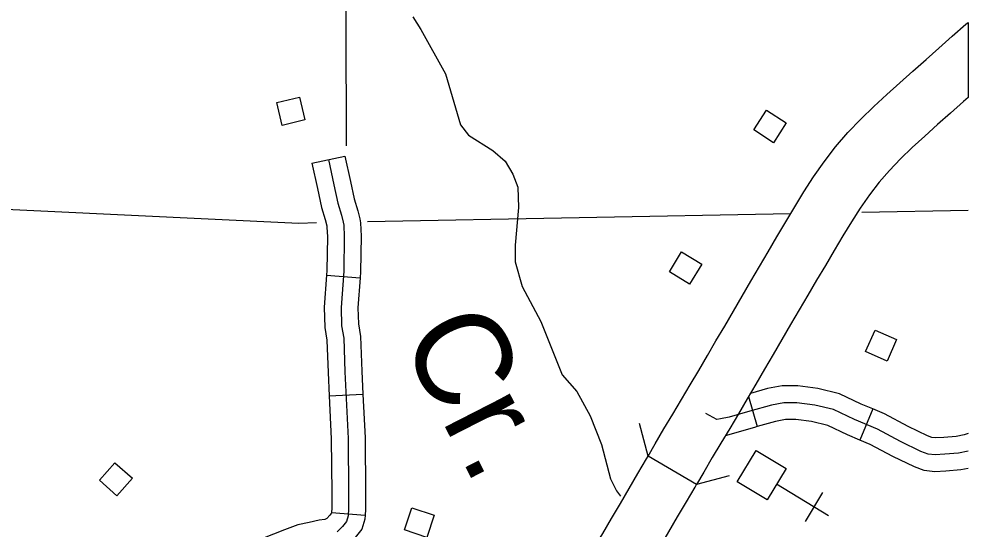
# Model space of a CAD drawing. Extents: x 1370130 to 1380143, y 377636 to 380256.
# Drawn here: x 1377650 to 1377768.2, y 379128.7 to 379192.1 of the extents above; entities that cross this region are included whole.
import ezdxf

# ---------------------------------------------------------------- set-up
doc = ezdxf.new("R2010")
doc.units = 0
for name, color, linetype in [('Level 15', 7, 'Continuous'), ('Level 32', 7, 'Continuous'), ('Level 35', 7, 'Continuous'), ('Level 37', 7, 'Continuous'), ('Level 4', 7, 'Continuous'), ('Level 5', 7, 'Continuous'), ('Level 56', 7, 'Continuous'), ('Level 57', 7, 'Continuous')]:
    doc.layers.add(name, color=color, linetype=linetype)

msp = doc.modelspace()

# ---------------------------------------------------------------- linework, layer by layer
at = {"layer": 'Level 15'}
for p, q in [((1377767.86, 379191.46), (1377768.15, 379191.69)), ((1377768.15, 379191.69), (1377768.15, 379182.36)), ((1377766.16, 379189.98), (1377767.86, 379191.46)), ((1377764.53, 379188.51), (1377766.16, 379189.98)), ((1377762.92, 379187.07), (1377764.53, 379188.51)), ((1377761.3, 379185.64), (1377762.92, 379187.07)), ((1377759.68, 379184.19), (1377761.3, 379185.64)), ((1377758.06, 379182.74), (1377759.68, 379184.19)), ((1377756.42, 379181.24), (1377758.06, 379182.74)), ((1377768.15, 379182.36), (1377767.57, 379181.84)), ((1377754.79, 379179.67), (1377756.42, 379181.24)), ((1377767.57, 379181.84), (1377765.95, 379180.41)), ((1377765.95, 379180.41), (1377764.35, 379178.98)), ((1377753.19, 379178), (1377754.79, 379179.67)), ((1377764.35, 379178.98), (1377762.76, 379177.55)), ((1377751.65, 379176.22), (1377753.19, 379178)), ((1377762.76, 379177.55), (1377761.21, 379176.13)), ((1377750.24, 379174.36), (1377751.65, 379176.22)), ((1377761.21, 379176.13), (1377759.74, 379174.72)), ((1377748.93, 379172.5), (1377750.24, 379174.36)), ((1377759.74, 379174.72), (1377758.36, 379173.28)), ((1377758.36, 379173.28), (1377757.09, 379171.81)), ((1377747.71, 379170.61), (1377748.93, 379172.5)), ((1377757.09, 379171.81), (1377755.89, 379170.23)), ((1377746.57, 379168.74), (1377747.71, 379170.61)), ((1377755.89, 379170.23), (1377754.73, 379168.59)), ((1377745.46, 379166.88), (1377746.57, 379168.74)), ((1377754.73, 379168.59), (1377753.64, 379166.89)), ((1377744.36, 379165.01), (1377745.46, 379166.88)), ((1377753.64, 379166.89), (1377752.56, 379165.12)), ((1377743.27, 379163.16), (1377744.36, 379165.01)), ((1377752.56, 379165.12), (1377751.48, 379163.31)), ((1377742.19, 379161.34), (1377743.27, 379163.16)), ((1377751.48, 379163.31), (1377750.39, 379161.46)), ((1377741.11, 379159.51), (1377742.19, 379161.34)), ((1377750.39, 379161.46), (1377749.3, 379159.61)), ((1377749.3, 379159.61), (1377748.22, 379157.77)), ((1377740.02, 379157.65), (1377741.11, 379159.51)), ((1377738.93, 379155.78), (1377740.02, 379157.65)), ((1377748.22, 379157.77), (1377747.14, 379155.95)), ((1377737.85, 379153.92), (1377738.93, 379155.78)), ((1377747.14, 379155.95), (1377746.06, 379154.12)), ((1377736.76, 379152.07), (1377737.85, 379153.92)), ((1377746.06, 379154.12), (1377744.98, 379152.26)), ((1377735.7, 379150.23), (1377736.76, 379152.07)), ((1377744.98, 379152.26), (1377743.89, 379150.39)), ((1377734.63, 379148.4), (1377735.7, 379150.23)), ((1377743.89, 379150.39), (1377742.82, 379148.55)), ((1377733.55, 379146.58), (1377734.63, 379148.4)), ((1377742.82, 379148.55), (1377741.75, 379146.7)), ((1377741.75, 379146.7), (1377740.66, 379144.85)), ((1377732.48, 379144.77), (1377733.55, 379146.58)), ((1377731.39, 379142.96), (1377732.48, 379144.77)), ((1377740.66, 379144.85), (1377739.57, 379143.01)), ((1377730.29, 379141.12), (1377731.39, 379142.96)), ((1377739.57, 379143.01), (1377738.48, 379141.18)), ((1377729.2, 379139.27), (1377730.29, 379141.12)), ((1377738.48, 379141.18), (1377737.39, 379139.36)), ((1377728.31, 379137.74), (1377729.2, 379139.27)), ((1377737.39, 379139.36), (1377736.31, 379137.54)), ((1377734.36, 379134.21), (1377728.31, 379137.74)), ((1377736.31, 379137.54), (1377735.24, 379135.73)), ((1377735.24, 379135.73), (1377734.36, 379134.21))]:
    msp.add_line(p, q, dxfattribs=at)
for points in [[(1377720.96, 379125.36), (1377721.6, 379126.35), (1377722.68, 379128.12), (1377723.76, 379129.97), (1377724.86, 379131.85), (1377725.95, 379133.72), (1377727.04, 379135.56), (1377728.12, 379137.41), (1377728.31, 379137.74)], [(1377726.81, 379121.52), (1377727.53, 379122.61), (1377728.7, 379124.54), (1377729.81, 379126.45), (1377730.9, 379128.31), (1377731.99, 379130.17), (1377733.08, 379132.03), (1377734.16, 379133.88), (1377734.36, 379134.21)]]:
    msp.add_lwpolyline(points, dxfattribs=at)
at = {"layer": 'Level 32'}
for p, q in [((1377686.45, 379174.18), (1377690.56, 379175.07)), ((1377688.27, 379160.23), (1377692.46, 379159.91)), ((1377688.6, 379145.22), (1377692.8, 379145.43)), ((1377740.82, 379145.13), (1377741.89, 379141.4)), ((1377756.29, 379143.6), (1377754.68, 379139.73)), ((1377688.89, 379130.71), (1377693.08, 379130.39))]:
    msp.add_line(p, q, dxfattribs=at)
for points in [[(1377690.56, 379175.07), (1377691.24, 379171.92), (1377691.7, 379169.75), (1377692.17, 379168.27), (1377692.4, 379167.26), (1377692.51, 379166.74), (1377692.59, 379165.08), (1377692.52, 379160.64), (1377692.46, 379159.91)], [(1377686.45, 379174.18), (1377687.13, 379171.03), (1377687.63, 379168.68), (1377688.12, 379167.16), (1377688.3, 379166.38), (1377688.33, 379166.22), (1377688.39, 379165.01), (1377688.32, 379160.83), (1377688.27, 379160.23)], [(1377688.5, 379174.62), (1377689.19, 379171.48), (1377689.67, 379169.22), (1377690.15, 379167.71), (1377690.35, 379166.82), (1377690.42, 379166.48), (1377690.49, 379165.04), (1377690.42, 379160.73), (1377690.08, 379156.22), (1377690.15, 379153.96), (1377690.42, 379152.39), (1377690.56, 379148.21), (1377690.97, 379139.94), (1377691.03, 379133.16), (1377691.03, 379131.18), (1377690.97, 379130.29), (1377690.76, 379129.6), (1377690.28, 379128.99), (1377689.6, 379128.3)], [(1377688.27, 379160.23), (1377687.97, 379156.27), (1377688.05, 379153.75), (1377688.32, 379152.17), (1377688.46, 379148.13), (1377688.6, 379145.22)], [(1377692.46, 379159.91), (1377692.18, 379156.17), (1377692.24, 379154.17), (1377692.51, 379152.6), (1377692.65, 379148.3), (1377692.8, 379145.43)], [(1377692.8, 379145.43), (1377693.07, 379140), (1377693.13, 379133.17), (1377693.13, 379131.1), (1377693.08, 379130.39)], [(1377756.29, 379143.6), (1377754.85, 379144.2), (1377752.13, 379145.5), (1377749.45, 379146.16), (1377746.97, 379146.48), (1377745.03, 379146.48), (1377743.19, 379146.14), (1377741.07, 379145.53)], [(1377688.6, 379145.22), (1377688.87, 379139.87), (1377688.93, 379133.15), (1377688.93, 379131.26), (1377688.89, 379130.71)], [(1377768.15, 379138.33), (1377766.96, 379138.09), (1377765.25, 379137.96), (1377764.06, 379137.9), (1377763.19, 379137.99), (1377762.28, 379138.32), (1377759.74, 379139.54), (1377756.87, 379141.09), (1377754, 379142.28), (1377751.42, 379143.51), (1377749.06, 379144.09), (1377746.84, 379144.38), (1377745.22, 379144.38), (1377743.68, 379144.09), (1377740.97, 379143.32), (1377738.42, 379142.57), (1377737.32, 379142.38), (1377736.87, 379142.28), (1377735.52, 379143.04)], [(1377768.15, 379140.55), (1377767.66, 379140.38), (1377766.67, 379140.17), (1377765.12, 379140.06), (1377764.12, 379140), (1377763.66, 379140.05), (1377763.09, 379140.26), (1377760.69, 379141.41), (1377757.77, 379142.99), (1377756.29, 379143.6)], [(1377754.68, 379139.73), (1377753.14, 379140.37), (1377750.71, 379141.52), (1377748.67, 379142.02), (1377746.7, 379142.28), (1377745.42, 379142.28), (1377744.16, 379142.05), (1377741.89, 379141.4)], [(1377741.89, 379141.4), (1377741.55, 379141.3), (1377737.93, 379140.24)], [(1377768.15, 379136.19), (1377767.25, 379136.01), (1377765.39, 379135.86), (1377764, 379135.79), (1377762.71, 379135.93), (1377761.47, 379136.38), (1377758.78, 379137.67), (1377755.96, 379139.19), (1377754.68, 379139.73)], [(1377688.89, 379130.71), (1377688.89, 379130.68), (1377688.86, 379130.58), (1377688.7, 379130.38), (1377688.3, 379129.98), (1377688.08, 379129.85), (1377687.37, 379129.76), (1377686.13, 379129.47), (1377684.71, 379129.17), (1377683.04, 379128.56), (1377680.28, 379127.47), (1377677.99, 379126.17), (1377677.25, 379125.62)], [(1377693.08, 379130.39), (1377693.04, 379129.9), (1377692.66, 379128.63), (1377691.86, 379127.6), (1377690.89, 379126.63), (1377689.47, 379125.8), (1377688.13, 379125.62), (1377687.05, 379125.37), (1377685.87, 379125.12), (1377684.53, 379124.63), (1377682.1, 379123.67), (1377680.28, 379122.64), (1377679.74, 379122.24)]]:
    msp.add_lwpolyline(points, dxfattribs=at)
at = {"layer": 'Level 35'}
msp.add_lwpolyline([(1377699.04, 379192.4), (1377700.03, 379190.82), (1377703.09, 379185.3), (1377704.96, 379178.94), (1377705.94, 379177.67), (1377708.99, 379175.77), (1377710.5, 379174.43), (1377711.46, 379172.82), (1377712.08, 379171.21), (1377712.19, 379168.68), (1377711.75, 379163.96), (1377711.77, 379161.91), (1377712.62, 379158.84), (1377714.95, 379154.46), (1377717.62, 379147.84), (1377719.46, 379145.77), (1377721.12, 379142.75), (1377722.51, 379139.16), (1377723.64, 379134.91), (1377724.37, 379133.41), (1377724.88, 379132.75)], dxfattribs=at)
at = {"layer": 'Level 37'}
for points in [[(1377728.31, 379137.74), (1377727.24, 379141.8)], [(1377738.42, 379135.28), (1377734.36, 379134.21)]]:
    msp.add_lwpolyline(points, dxfattribs=at)
at = {"layer": 'Level 4'}
for points in [[(1377687.01, 379166.75), (1377684.84, 379166.69), (1377545.86, 379173.3), (1377543.53, 379173.41), (1377537.66, 379173.5)], [(1377746.07, 379167.87), (1377693.38, 379166.89)], [(1377768.15, 379168.29), (1377754.91, 379168.04)]]:
    msp.add_lwpolyline(points, dxfattribs=at)
at = {"layer": 'Level 5'}
msp.add_lwpolyline([(1377690.46, 379268.93), (1377690.72, 379176.34)], dxfattribs=at)
at = {"layer": 'Level 56'}
for points in [[(1377684.91, 379182.39), (1377685.59, 379179.56), (1377682.74, 379178.88), (1377682.07, 379181.71)], [(1377741.49, 379178.31), (1377743.06, 379180.76), (1377745.52, 379179.19), (1377743.95, 379176.73)], [(1377734.99, 379161.63), (1377733.46, 379159.14), (1377730.97, 379160.67), (1377732.49, 379163.15)], [(1377759.24, 379152.23), (1377758.07, 379149.56), (1377755.39, 379150.74), (1377756.57, 379153.41)], [(1377664.11, 379134.97), (1377662.17, 379132.79), (1377659.99, 379134.74), (1377661.93, 379136.91)], [(1377697.99, 379128.55), (1377698.91, 379131.31), (1377701.69, 379130.39), (1377700.76, 379127.62)]]:
    msp.add_lwpolyline(points, close=True, dxfattribs=at)
at = {"layer": 'Level 57'}
for p, q in [((1377750.76, 379130.31), (1377744.31, 379134.22)), ((1377750.05, 379133.2), (1377747.88, 379129.61))]:
    msp.add_line(p, q, dxfattribs=at)
msp.add_lwpolyline([(1377741.76, 379138.43), (1377745.49, 379136.17), (1377743.14, 379132.29), (1377739.41, 379134.55)], close=True, dxfattribs=at)

# ---------------------------------------------------------------- texts
at = {"layer": 'Level 35'}
msp.add_text('Cr.', height=11.827, rotation=297.0639, dxfattribs=at).set_placement((1377697.33, 379152.5))

doc.saveas('drawing.dxf')
